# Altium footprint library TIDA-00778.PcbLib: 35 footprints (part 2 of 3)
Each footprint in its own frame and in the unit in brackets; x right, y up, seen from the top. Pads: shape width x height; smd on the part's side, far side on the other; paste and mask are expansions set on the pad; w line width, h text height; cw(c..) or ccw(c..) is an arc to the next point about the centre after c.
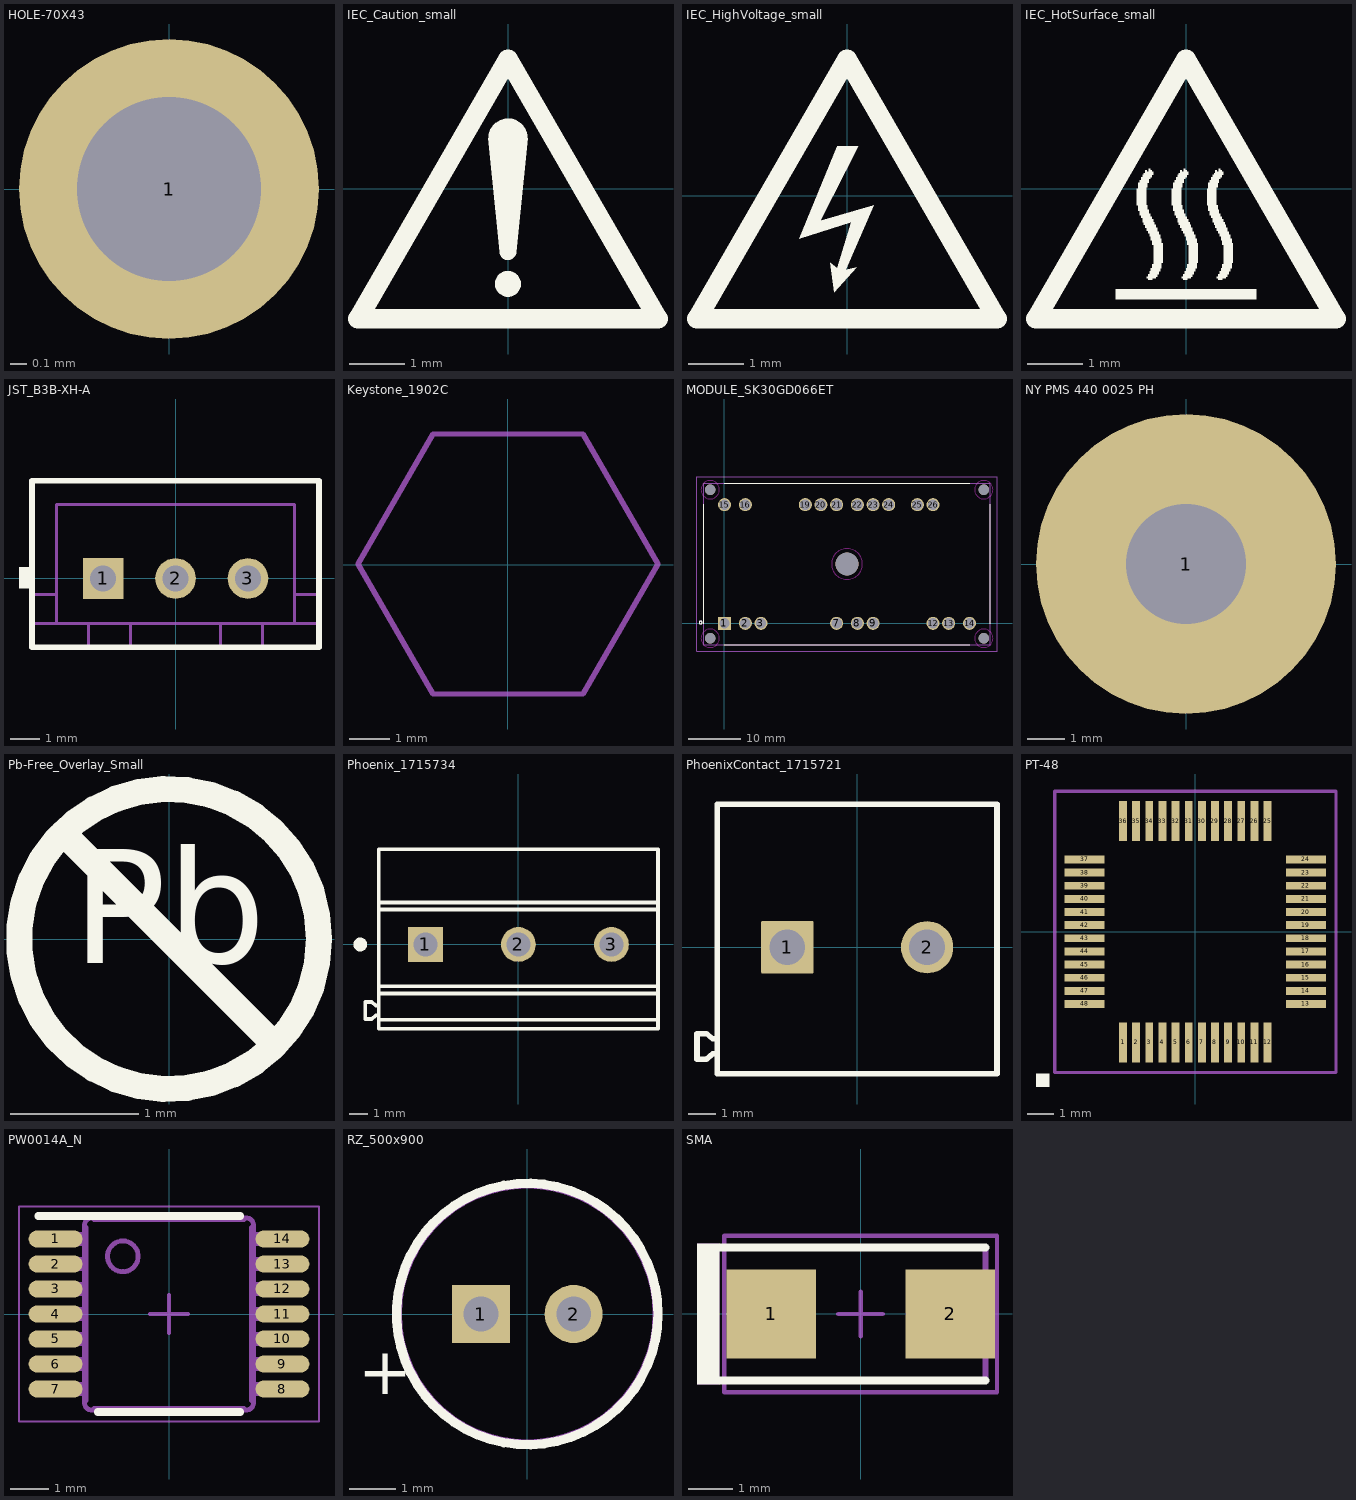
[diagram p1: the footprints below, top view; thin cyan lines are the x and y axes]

## HOLE-70X43 [mil]
pads (1):
  round 70 hole 43: 1(0,0)

## IEC_Caution_small [mm]
Top Overlay:
  circle w0.254: c0,-1.727 r0.108
  circle w0.356: c0,0.914 r0.178
  circle w0.254: c0,-1.143 r0.025
  region: -0.356,0.914 0.356,0.914 0.152,-1.143 -0.152,-1.143
  lines w0.356: -2.718,-2.362 0,2.345 2.718,-2.362 -2.718,-2.362

## IEC_HighVoltage_small [mm]
Top Overlay:
  region: -0.178,0.889 0.203,0.889 -0.483,-0.457 0.483,-0.178 -0.025,-1.346 0.178,-1.295 -0.229,-1.753 -0.305,-1.219 -0.178,-1.321 0.076,-0.483 -0.864,-0.787
  lines w0.356: -2.718,-2.235 0,2.472 2.718,-2.235 -2.718,-2.235

## IEC_HotSurface_small [mm]
height 0.889
Top Overlay:
  drawing of 10 lines, arcs and shapes, not listed

## JST_B3B-XH-A [mm] "Header (Shrouded), 2.5mm, 3x1, TH"
height 7
pads (3):
  rect 1.4x1.4 hole 0.9: 1(-2.5,0)
  round 1.4 hole 0.9: 2(0,0) 3(2.5,0)
Top Layer:
  lines w0.1: -0.32,-0.32 0,0 ; -0.32,0.32 0,0 ; 0.32,-0.32 0,0 ; 0.32,0.32 0,0
Top Overlay:
  rectangle: -5.4,-0.347 -5.05,0.403
  lines w0.2: -4.95,-2.375 -4.95,-1.55 -4.95,-0.55 -4.95,3.375 4.95,3.375 4.95,-0.55 4.95,-1.55 4.95,-2.375 3,-2.375 1.55,-2.375 -1.55,-2.375 -3,-2.375 -4.95,-2.375
Mechanical 5:
  lines w0.1: -4.1,-1.55 -4.1,-0.55 ; 4.1,-1.55 4.1,-0.55 ; -4.95,-1.55 -3,-1.55 ; -4.95,-1.55 -4.95,-0.55 ; -4.95,-1.55 -4.95,-2.375 -3,-2.375 ; -4.95,-0.55 -4.1,-0.55 ; -4.95,-0.55 -4.95,3.375 4.95,3.375 4.95,-0.55 ; -4.1,-0.55 -4.1,2.55 4.1,2.55 4.1,-0.55 ; -3,-2.375 -3,-1.55 ; -3,-2.375 -1.55,-2.375 ; -3,-1.55 -1.55,-1.55 ; -1.55,-2.375 -1.55,-1.55 ; -1.55,-2.375 1.55,-2.375 ; -1.55,-1.55 1.55,-1.55 ; 1.55,-2.375 3,-2.375 ; 1.55,-2.375 1.55,-1.55 ; 1.55,-1.55 3,-1.55 ; 3,-2.375 3,-1.55 ; 3,-2.375 4.95,-2.375 4.95,-1.55 ; 3,-1.55 4.95,-1.55 ; 4.1,-0.55 4.95,-0.55 ; 4.95,-1.55 4.95,-0.55
  text ".Designator" at -0.293,1.041 h0.76
3D body "B3B-XH-A.stp": height 7, standoff -3.4, extent -4.95,-2.375 4.95,3.375

## Keystone_1902C [mil] "Hex Standoff, 4-40 threaded, nylon"
height 500
pads (1):
  round 1 on Mech3: 0(0,0)
Mechanical 5:
  lines w5: -145.29,0.49 -72.56,-125.49 72.92,-125.49 145.65,0.49 72.92,126.47 -72.56,126.47 -145.29,0.49
  text ".Designator" at -24,-4.55 h30
3D body "Keystone_1902C.stp": height 501, standoff 1, extent -144.95,-125.98 146,125.98

## MODULE_SK30GD066ET [mm] "MODULE, TH-19P"
height 12
pads (24):
  rect 2.5x2.5 / inner round 2.5 / far side rect 2.5x2.5 hole 2: 1(0,0)
  round 2.5 hole 2: 2(4,0) 3(7,0) 7(21.5,0) 8(25.5,0) 9(28.5,0) 12(40,0) 13(43,0) 14(47,0) 15(0,22.75) 16(4,22.75) 19(15.5,22.75) 20(18.5,22.75) 21(21.5,22.75) 22(25.5,22.75) 23(28.5,22.75) 24(31.5,22.75) 25(37,22.75) 26(40,22.75)
  round 2 hole 2 unplated: ""(-2.75,-2.875) ""(-2.75,25.625) ""(49.75,-2.875) ""(49.75,25.625)
  round 4.4 hole 4.4 unplated: ""(23.5,11.375)
Top Overlay:
  circle w0.178: c-4.584,0.152 r0.279
  lines w0.178: -4,-0.125 -4,22.875 ; 0,-4.125 47,-4.125 ; 0,26.875 47,26.875 ; 51,-0.125 51,22.875
  text ".Designator" at 21.976,28.375 h1.02
Bottom Overlay:
  lines w0.178: -4,-1.013 -4,2.987 ; -4,5.362 -4,9.362 ; -4,12.195 -4,16.195 ; -4,18.799 -4,22.799 ; 0,-4.125 4,-4.125 ; 0,26.875 4,26.875 ; 7.62,-4.125 11.62,-4.125 ; 7.62,26.875 11.62,26.875 ; 14.986,-4.125 18.986,-4.125 ; 14.986,26.875 18.986,26.875 ; 22.606,-4.125 26.606,-4.125 ; 22.606,26.875 26.606,26.875 ; 29.972,-4.125 33.972,-4.125 ; 29.972,26.875 33.972,26.875 ; 37.084,-4.125 41.084,-4.125 ; 37.084,26.875 41.084,26.875 ; 43.942,-4.125 47.942,-4.125 ; 43.942,26.875 47.942,26.875 ; 51,-0.88 51,3.12 ; 51,5.533 51,9.533 ; 51,12.264 51,16.264 ; 51,18.875 51,22.875
Keep-Out Layer:
  circle w0.05: c23.5,11.375 r2.962
  circle w0.05: c-2.75,-2.875 r1.762
  circle w0.05: c49.75,-2.875 r1.762
  circle w0.05: c49.75,25.625 r1.762
  circle w0.05: c-2.75,25.625 r1.762
Mechanical 5:
  circle w0.127: c-4.584,0.152 r0.279
  lines w0.127: -4,-4.125 -4,26.875 51,26.875 51,-4.125 -4,-4.125
  text ".Designator" at 21.976,10.867 h1.02
Mechanical 15:
  lines w0.05: -5.27,-5.395 52.27,-5.395 52.27,28.145 -5.27,28.145 -5.27,-5.395
Mechanical 17:
  text "LEAD LENGTH:3.5MM" at 10.165,5.152 h1.52
3D body: height 12, standoff 0, extent -4,-4.125 51,26.875

## NY PMS 440 0025 PH [mm] "4-40 nylon screw and mounting hole"
height 1.905
pads (1):
  round 8 hole 3.2: 1(0,0)
Mechanical 5:
  circle w0.127: c0,0 r3.789
  text ".Designator" at -1.524,-0.508 h0.76
3D body "B_F_NY PMS 440 0025 PH.stp": height 2.69, standoff -8.74, extent -3.302,-3.3 3.296,3.3

## Pb-Free_Overlay_Small [mm]
height 0.6
Top Overlay:
  circle w0.203: c0,0 r1.168
  lines w0.203: -0.826,0.826 0.826,-0.826
  text "Pb" at -0.752,-0.48 h1.52

## PCBComponent_1 [mm]

## Phoenix_1715734 [mm] "Phoenix"
height 13.8
pads (3):
  rect 1.9x1.9 hole 1.321: 1(-5.08,0)
  round 1.9 hole 1.321: 2(0,0) 3(5.08,0)
Top Overlay:
  circle w0.5: c-8.634,0 r0.125
  lines w0.2: -7.62,-3.869 -7.787,-3.869 -8.019,-4.064 -8.361,-4.064 -8.361,-3.136 -8.019,-3.136 -7.787,-3.331 -7.62,-3.331 ; -7.62,-4.1 7.62,-4.1 ; -7.62,-4.1 -7.62,-4.6 7.62,-4.6 7.62,-4.1 ; -7.62,-4.1 -7.62,-2.672 ; -7.62,-2.672 7.62,-2.672 ; -7.62,-2.672 -7.62,-2.283 ; -7.62,-2.283 7.62,-2.283 ; -7.62,-2.283 -7.62,1.909 ; -7.62,1.909 7.62,1.909 ; -7.62,1.909 -7.62,2.29 ; -7.62,2.29 7.62,2.29 ; -7.62,2.29 -7.62,5.2 7.62,5.2 7.62,2.29 ; 7.62,-4.1 7.62,-2.672 ; 7.62,-2.672 7.62,-2.283 ; 7.62,-2.283 7.62,1.909 ; 7.62,1.909 7.62,2.29
Mechanical 5:
  region: -6.025,0.95 -4.125,0.95 -4.125,-0.95 -6.025,-0.95
  lines w0.127: -7.62,-3.869 -7.787,-3.869 -8.019,-4.064 -8.361,-4.064 -8.361,-3.136 -8.019,-3.136 -7.787,-3.331 -7.62,-3.331 ; -7.62,-4.1 -7.62,-2.672 ; -7.62,-4.1 -7.62,-4.6 7.62,-4.6 7.62,-4.1 ; -7.62,-4.1 7.62,-4.1 ; -7.62,-2.672 -7.62,-2.283 ; -7.62,-2.672 7.62,-2.672 ; -7.62,-2.283 -7.62,1.909 ; -7.62,-2.283 7.62,-2.283 ; -7.62,1.909 -7.62,2.29 ; -7.62,1.909 7.62,1.909 ; -7.62,2.29 -7.62,5.2 7.62,5.2 7.62,2.29 ; -7.62,2.29 7.62,2.29 ; 7.62,-4.1 7.62,-2.672 ; 7.62,-2.672 7.62,-2.283 ; 7.62,-2.283 7.62,1.909 ; 7.62,1.909 7.62,2.29
  text ".Designator" at -2.245,-0.175 h1.02
3D body "Phoenix_1715734.stp": height 14.2, standoff -3.5, extent -8.361,-4.6 7.62,5.2

## PhoenixContact_1715721 [mm] "Phoenix Contact 1715721 used on LM3445 design from Longmont"
height 13.8
pads (2):
  rrect5% 1.905x1.905 hole 1.3: 1(-2.54,0)
  round 1.9 hole 1.3: 2(2.54,0)
Top Overlay:
  lines w0.2: -5.08,-3.869 -5.247,-3.869 -5.479,-4.064 -5.821,-4.064 -5.821,-3.136 -5.479,-3.136 -5.247,-3.331 -5.08,-3.331 ; -5.08,-4.6 -5.08,5.2 5.08,5.2 5.08,-4.6 -5.08,-4.6
Mechanical 5:
  lines w0.1: -5.08,-3.869 -5.247,-3.869 -5.479,-4.064 -5.821,-4.064 -5.821,-3.136 -5.479,-3.136 -5.247,-3.331 -5.08,-3.331 ; -5.08,-4.6 5.08,-4.6 5.08,5.2 -5.08,5.2 -5.08,-4.6
  text ".Designator" at 0.497,-0.282 h0.76
3D body "1715721.stp": height 14.2, standoff -3.5, extent -5.817,-4.598 5.084,5.202

## PT-48 [mil]
pads (48):
  rect 11.81x60 smd mask+1.97: 1(-108.4,-165.9) 2(-88.7,-165.9) 3(-69,-165.9) 4(-49.3,-165.9) 5(-29.6,-165.9) 6(-9.9,-165.9) 7(9.8,-165.9) 8(29.5,-165.9) 9(49.2,-165.9) 10(68.9,-165.9) 11(88.6,-165.9) 12(108.3,-165.9) 25(108.3,166.1) 26(88.6,166.1) 27(68.9,166.1) 28(49.2,166.1) 29(29.5,166.1) 30(9.8,166.1) 31(-9.9,166.1) 32(-29.6,166.1) 33(-49.3,166.1) 34(-69,166.1) 35(-88.7,166.1) 36(-108.4,166.1)
  rect 60x11.81 smd mask+1.97: 13(166,-108.2) 14(166,-88.5) 15(166,-68.8) 16(166,-49.1) 17(166,-29.4) 18(166,-9.7) 19(166,10) 20(166,29.7) 21(166,49.4) 22(166,69.1) 23(166,88.8) 24(166,108.5) 37(-165.9,108.5) 38(-165.9,88.8) 39(-165.9,69.1) 40(-165.9,49.4) 41(-165.9,29.7) 42(-165.9,10) 43(-165.9,-9.7) 44(-165.9,-29.4) 45(-165.9,-49.1) 46(-165.9,-68.8) 47(-165.9,-88.5) 48(-165.9,-108.2)
Top Overlay:
  region: -238.9,-232.5 -218.9,-232.5 -218.9,-212.5 -238.9,-212.5
Mechanical 5:
  lines w5: -211,-211 211,-211 211,211 -211,211 -211,-211
  text "*" at -190,-200 h30
  text ".Designator" at -73,-20 h40

## PW0014A_N [mm] "TSOP, 14-Leads, Body 5x4.4mm, Pitch 0.65mm, IPC Medium Density"
height 1.2
pads (14):
  oval 1.4x0.45 smd: 1(-2.95,1.95) 2(-2.95,1.3) 3(-2.95,0.65) 4(-2.95,0) 5(-2.95,-0.65) 6(-2.95,-1.3) 7(-2.95,-1.95) 8(2.95,-1.95) 9(2.95,-1.3) 10(2.95,-0.65) 11(2.95,0) 12(2.95,0.65) 13(2.95,1.3) 14(2.95,1.95)
Top Overlay:
  lines w0.2: -3.4,2.55 1.85,2.55 ; -1.85,-2.55 1.85,-2.55
Mechanical 5:
  drawing of 182 lines, arcs and shapes, not listed
  text ".Designator" at -0.275,1.9 h1.02
Mechanical 15:
  lines w0.05: -3.9,-2.8 -3.9,2.8 3.9,2.8 3.9,-2.8 -3.9,-2.8
  lines w0.1: -0.5,0 0.5,0 ; 0,-0.5 0,0.5
3D body "PW0014A.stp": height 1, standoff 0, extent -3.21,-2.5 3.21,2.5

## RZ_500x900 [mm] "NICHICON"
height 10.5
pads (2):
  rect 1.25x1.25 hole 0.75: 1(-1,0)
  round 1.25 hole 0.75: 2(1,0)
Top Overlay:
  circle w0.2: c0,0 r2.816
  text "+" at -3.646,-1.727 h1.02
Mechanical 5:
  circle w0.1: c0,0 r2.75
  text "+" at -3.9,-0.5 h0.76
  text ".Designator" at -0.522,0.838 h0.76
3D body "RZ_500x900.stp": height 10.51, standoff -4, extent -2.728,-2.745 2.75,2.746

## SMA [mm] "Molded Diode, 2-Leads, Body 4.3x2.6mm, IPC Medium Density, based on OnSemi component dimensions and land pattern"
height 2.27
pads (2):
  rect 2x2 smd: 1(-2,0) 2(2,0)
Top Overlay:
  rectangle: -3.658,-1.575 -3.15,1.575
  lines w0.178: -3.327,-1.486 2.794,-1.486 ; -3.327,1.486 2.794,1.486
Mechanical 5:
  rectangle: -3.658,-1.575 -3.15,1.575
  lines w0.127: -3.327,-1.486 2.794,-1.486 2.794,1.486 -3.327,1.486
  text ".Designator" at -0.076,0.457 h0.76
Mechanical 15:
  lines w0.1: -0.5,0 0.5,0 ; 0,-0.5 0,0.5 ; -3.05,-1.75 3.05,-1.75 3.05,1.75 -3.05,1.75 -3.05,-1.75
3D body "SMA_nominal.stp": height 2.42, standoff 0.02, extent -2.6,-1.3 2.6,1.3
